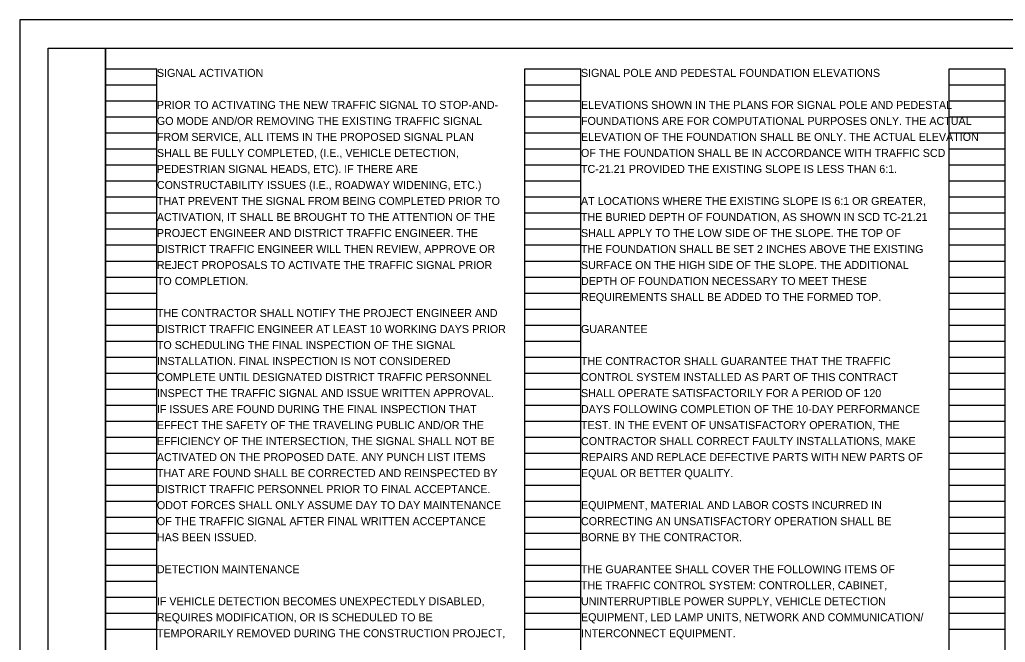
# Model space of a CAD drawing. Extents: x 0 to 34, y 0 to 22.
# Drawn here: x 0 to 17.24, y 11.11 to 22 of the extents above; entities that cross this region are included whole.
import ezdxf

# ---------------------------------------------------------------- set-up
doc = ezdxf.new("R2010")
doc.units = 0
for name, color, linetype in [('SH_Border', 7, 'Continuous'), ('SH_Cut_Line', 7, 'Continuous'), ('SH_Data', 7, 'Continuous'), ('SH_Text', 7, 'Continuous')]:
    doc.layers.add(name, color=color, linetype=linetype)

msp = doc.modelspace()

# ---------------------------------------------------------------- linework, layer by layer
at = {"layer": 'SH_Border'}
for points in [[(0.5, 21.5), (1.5, 21.5), (1.5, 0.5), (0.5, 0.5)], [(1.5, 21.5), (33.5, 21.5), (33.5, 0.5), (1.5, 0.5)]]:
    msp.add_lwpolyline(points, close=True, dxfattribs=at)
at = {"layer": 'SH_Cut_Line'}
msp.add_lwpolyline([(0, 0), (34, 0), (34, 22), (0, 22)], close=True, dxfattribs=at)
at = {"layer": 'SH_Data'}
for p, q in [((1.5, 0.98), (1.5, 21.14)), ((1.5, 21.14), (2.4, 21.14)), ((2.4, 0.98), (2.4, 21.14)), ((8.84, 0.98), (8.84, 21.14)), ((8.84, 21.14), (9.82, 21.14)), ((9.82, 0.98), (9.82, 21.14)), ((16.26, 0.98), (16.26, 21.14)), ((16.26, 21.14), (17.24, 21.14)), ((17.24, 0.98), (17.24, 21.14)), ((1.5, 20.86), (2.4, 20.86)), ((8.84, 20.86), (9.82, 20.86)), ((16.26, 20.86), (17.24, 20.86)), ((1.5, 20.58), (2.4, 20.58)), ((8.84, 20.58), (9.82, 20.58)), ((16.26, 20.58), (17.24, 20.58)), ((1.5, 20.3), (2.4, 20.3)), ((8.84, 20.3), (9.82, 20.3)), ((16.26, 20.3), (17.24, 20.3)), ((1.5, 20.02), (2.4, 20.02)), ((8.84, 20.02), (9.82, 20.02)), ((16.26, 20.02), (17.24, 20.02)), ((1.5, 19.74), (2.4, 19.74)), ((8.84, 19.74), (9.82, 19.74)), ((16.26, 19.74), (17.24, 19.74)), ((1.5, 19.46), (2.4, 19.46)), ((8.84, 19.46), (9.82, 19.46)), ((16.26, 19.46), (17.24, 19.46)), ((1.5, 19.18), (2.4, 19.18)), ((8.84, 19.18), (9.82, 19.18)), ((16.26, 19.18), (17.24, 19.18)), ((1.5, 18.9), (2.4, 18.9)), ((8.84, 18.9), (9.82, 18.9)), ((16.26, 18.9), (17.24, 18.9)), ((1.5, 18.62), (2.4, 18.62)), ((8.84, 18.62), (9.82, 18.62)), ((16.26, 18.62), (17.24, 18.62)), ((1.5, 18.34), (2.4, 18.34)), ((8.84, 18.34), (9.82, 18.34)), ((16.26, 18.34), (17.24, 18.34)), ((1.5, 18.06), (2.4, 18.06)), ((8.84, 18.06), (9.82, 18.06)), ((16.26, 18.06), (17.24, 18.06)), ((1.5, 17.78), (2.4, 17.78)), ((8.84, 17.78), (9.82, 17.78)), ((16.26, 17.78), (17.24, 17.78)), ((1.5, 17.5), (2.4, 17.5)), ((8.84, 17.5), (9.82, 17.5)), ((16.26, 17.5), (17.24, 17.5)), ((1.5, 17.22), (2.4, 17.22)), ((8.84, 17.22), (9.82, 17.22)), ((16.26, 17.22), (17.24, 17.22)), ((1.5, 16.94), (2.4, 16.94)), ((8.84, 16.94), (9.82, 16.94)), ((16.26, 16.94), (17.24, 16.94)), ((1.5, 16.66), (2.4, 16.66)), ((8.84, 16.66), (9.82, 16.66)), ((16.26, 16.66), (17.24, 16.66)), ((1.5, 16.38), (2.4, 16.38)), ((8.84, 16.38), (9.82, 16.38)), ((16.26, 16.38), (17.24, 16.38)), ((1.5, 16.1), (2.4, 16.1)), ((8.84, 16.1), (9.82, 16.1)), ((16.26, 16.1), (17.24, 16.1)), ((1.5, 15.82), (2.4, 15.82)), ((8.84, 15.82), (9.82, 15.82)), ((16.26, 15.82), (17.24, 15.82)), ((1.5, 15.54), (2.4, 15.54)), ((8.84, 15.54), (9.82, 15.54)), ((16.26, 15.54), (17.24, 15.54)), ((1.5, 15.26), (2.4, 15.26)), ((8.84, 15.26), (9.82, 15.26)), ((16.26, 15.26), (17.24, 15.26)), ((1.5, 14.98), (2.4, 14.98)), ((8.84, 14.98), (9.82, 14.98)), ((16.26, 14.98), (17.24, 14.98)), ((1.5, 14.7), (2.4, 14.7)), ((8.84, 14.7), (9.82, 14.7)), ((16.26, 14.7), (17.24, 14.7)), ((1.5, 14.42), (2.4, 14.42)), ((8.84, 14.42), (9.82, 14.42)), ((16.26, 14.42), (17.24, 14.42)), ((1.5, 14.14), (2.4, 14.14)), ((8.84, 14.14), (9.82, 14.14)), ((16.26, 14.14), (17.24, 14.14)), ((1.5, 13.86), (2.4, 13.86)), ((8.84, 13.86), (9.82, 13.86)), ((16.26, 13.86), (17.24, 13.86)), ((1.5, 13.58), (2.4, 13.58)), ((8.84, 13.58), (9.82, 13.58)), ((16.26, 13.58), (17.24, 13.58)), ((1.5, 13.3), (2.4, 13.3)), ((8.84, 13.3), (9.82, 13.3)), ((16.26, 13.3), (17.24, 13.3)), ((1.5, 13.02), (2.4, 13.02)), ((8.84, 13.02), (9.82, 13.02)), ((16.26, 13.02), (17.24, 13.02)), ((1.5, 12.74), (2.4, 12.74)), ((8.84, 12.74), (9.82, 12.74)), ((16.26, 12.74), (17.24, 12.74)), ((1.5, 12.46), (2.4, 12.46)), ((8.84, 12.46), (9.82, 12.46)), ((16.26, 12.46), (17.24, 12.46)), ((1.5, 12.18), (2.4, 12.18)), ((8.84, 12.18), (9.82, 12.18)), ((16.26, 12.18), (17.24, 12.18)), ((1.5, 11.9), (2.4, 11.9)), ((8.84, 11.9), (9.82, 11.9)), ((16.26, 11.9), (17.24, 11.9)), ((1.5, 11.62), (2.4, 11.62)), ((8.84, 11.62), (9.82, 11.62)), ((16.26, 11.62), (17.24, 11.62)), ((1.5, 11.34), (2.4, 11.34)), ((8.84, 11.34), (9.82, 11.34)), ((16.26, 11.34), (17.24, 11.34))]:
    msp.add_line(p, q, dxfattribs=at)

# ---------------------------------------------------------------- texts
at = {"layer": 'SH_Text'}
for s, p in [('SIGNAL ACTIVATION', (2.4, 21)), ('SIGNAL POLE AND PEDESTAL FOUNDATION ELEVATIONS', (9.82, 21)), ('PRIOR TO ACTIVATING THE NEW TRAFFIC SIGNAL TO STOP-AND-', (2.4, 20.44)), ('ELEVATIONS SHOWN IN THE PLANS FOR SIGNAL POLE AND PEDESTAL', (9.82, 20.44)), ('GO MODE AND/OR REMOVING THE EXISTING TRAFFIC SIGNAL', (2.4, 20.16)), ('FOUNDATIONS ARE FOR COMPUTATIONAL PURPOSES ONLY. THE ACTUAL ', (9.82, 20.16)), ('FROM SERVICE, ALL ITEMS IN THE PROPOSED SIGNAL PLAN', (2.4, 19.88)), ('ELEVATION OF THE FOUNDATION SHALL BE ONLY. THE ACTUAL ELEVATION ', (9.82, 19.88)), ('SHALL BE FULLY COMPLETED, (I.E., VEHICLE DETECTION,', (2.4, 19.6)), ('OF THE  ', (9.82, 19.6)), ('FOUNDATION SHALL BE IN ACCORDANCE WITH TRAFFIC SCD ', (10.568, 19.6)), ('PEDESTRIAN SIGNAL HEADS, ETC). IF THERE ARE', (2.4, 19.32)), ('TC-21.21 ', (9.82, 19.32)), ('PROVIDED THE EXISTING SLOPE IS LESS THAN 6:1.', (10.659, 19.32)), ('CONSTRUCTABILITY ISSUES (I.E., ROADWAY WIDENING, ETC.)', (2.4, 19.04)), ('THAT PREVENT THE SIGNAL FROM BEING COMPLETED PRIOR TO', (2.4, 18.76)), ('AT LOCATIONS WHERE THE EXISTING SLOPE IS 6:1 OR GREATER,', (9.82, 18.76)), ('ACTIVATION, IT SHALL BE BROUGHT TO THE ATTENTION OF THE', (2.4, 18.48)), ('THE BURIED DEPTH OF FOUNDATION, AS SHOWN IN SCD TC-21.21', (9.82, 18.48)), ('PROJECT ENGINEER AND DISTRICT TRAFFIC ENGINEER. THE', (2.4, 18.2)), ('SHALL APPLY TO THE LOW SIDE OF THE SLOPE. THE TOP OF', (9.82, 18.2)), ('DISTRICT TRAFFIC ENGINEER WILL THEN REVIEW, APPROVE OR', (2.4, 17.92)), ('THE FOUNDATION SHALL BE SET 2 INCHES ABOVE THE EXISTING', (9.82, 17.92)), ('REJECT PROPOSALS TO ACTIVATE THE TRAFFIC SIGNAL PRIOR', (2.4, 17.64)), ('SURFACE ON THE HIGH SIDE OF THE SLOPE. THE ADDITIONAL', (9.82, 17.64)), ('TO COMPLETION.', (2.4, 17.36)), ('DEPTH OF FOUNDATION NECESSARY TO MEET THESE', (9.82, 17.36)), ('REQUIREMENTS SHALL BE ADDED TO THE FORMED TOP.', (9.82, 17.08)), ('THE CONTRACTOR SHALL NOTIFY THE PROJECT ENGINEER AND', (2.4, 16.8)), ('DISTRICT TRAFFIC ENGINEER AT LEAST 10 WORKING DAYS PRIOR', (2.4, 16.52)), ('GUARANTEE', (9.82, 16.52)), ('TO SCHEDULING THE FINAL INSPECTION OF THE SIGNAL', (2.4, 16.24)), ('INSTALLATION. FINAL INSPECTION IS NOT CONSIDERED', (2.4, 15.96)), ('THE CONTRACTOR SHALL GUARANTEE THAT THE TRAFFIC', (9.82, 15.96)), ('COMPLETE UNTIL DESIGNATED DISTRICT TRAFFIC PERSONNEL', (2.4, 15.68)), ('CONTROL SYSTEM INSTALLED AS PART OF THIS CONTRACT', (9.82, 15.68)), ('INSPECT THE TRAFFIC SIGNAL AND ISSUE WRITTEN APPROVAL.', (2.4, 15.4)), ('SHALL OPERATE SATISFACTORILY FOR A PERIOD OF 120', (9.82, 15.4)), ('IF ISSUES ARE FOUND DURING THE FINAL INSPECTION THAT', (2.4, 15.12)), ('DAYS FOLLOWING COMPLETION OF THE 10-DAY PERFORMANCE', (9.82, 15.12)), ('EFFECT THE SAFETY OF THE TRAVELING PUBLIC AND/OR THE', (2.4, 14.84)), ('TEST. IN THE EVENT OF UNSATISFACTORY OPERATION, THE', (9.82, 14.84)), ('EFFICIENCY OF THE INTERSECTION, THE SIGNAL SHALL NOT BE', (2.4, 14.56)), ('CONTRACTOR SHALL CORRECT FAULTY INSTALLATIONS, MAKE', (9.82, 14.56)), ('ACTIVATED ON THE PROPOSED DATE. ANY PUNCH LIST ITEMS', (2.4, 14.28)), ('REPAIRS AND REPLACE DEFECTIVE PARTS WITH NEW PARTS OF', (9.82, 14.28)), ('THAT ARE FOUND SHALL BE CORRECTED AND REINSPECTED BY', (2.4, 14)), ('EQUAL OR BETTER QUALITY.', (9.82, 14)), ('DISTRICT TRAFFIC PERSONNEL PRIOR TO FINAL ACCEPTANCE.', (2.4, 13.72)), ('ODOT FORCES SHALL ONLY ASSUME DAY TO DAY MAINTENANCE', (2.4, 13.44)), ('EQUIPMENT, MATERIAL AND LABOR COSTS INCURRED IN', (9.82, 13.44)), ('OF THE TRAFFIC SIGNAL AFTER FINAL WRITTEN ACCEPTANCE', (2.4, 13.16)), ('CORRECTING AN UNSATISFACTORY OPERATION SHALL BE', (9.82, 13.16)), ('HAS BEEN ISSUED.', (2.4, 12.88)), ('BORNE BY THE CONTRACTOR.', (9.82, 12.88)), ('DETECTION MAINTENANCE', (2.4, 12.32)), ('THE GUARANTEE SHALL COVER THE FOLLOWING ITEMS OF', (9.82, 12.32)), ('THE TRAFFIC CONTROL SYSTEM: CONTROLLER, CABINET,', (9.82, 12.04)), ('IF VEHICLE DETECTION BECOMES UNEXPECTEDLY DISABLED,', (2.4, 11.76)), ('UNINTERRUPTIBLE POWER SUPPLY, VEHICLE DETECTION', (9.82, 11.76)), ('REQUIRES MODIFICATION, OR IS SCHEDULED TO BE', (2.4, 11.48)), ('EQUIPMENT, LED LAMP UNITS, NETWORK AND COMMUNICATION/', (9.82, 11.48)), ('TEMPORARILY REMOVED DURING THE CONSTRUCTION PROJECT,', (2.4, 11.2)), ('INTERCONNECT EQUIPMENT.', (9.82, 11.2))]:
    msp.add_text(s, height=0.14, dxfattribs=at).set_placement(p)

doc.saveas('drawing.dxf')
